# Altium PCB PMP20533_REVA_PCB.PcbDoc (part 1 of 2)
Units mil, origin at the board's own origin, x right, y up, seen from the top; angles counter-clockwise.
Board outline 2795.47 x 1881.89 mil, 4 copper layers (Top Layer, Signal Layer 1, Signal Layer 2, Bottom Layer), stack 40.634 mil thick; 90 components, 59 nets, 312 pads, 73 vias.
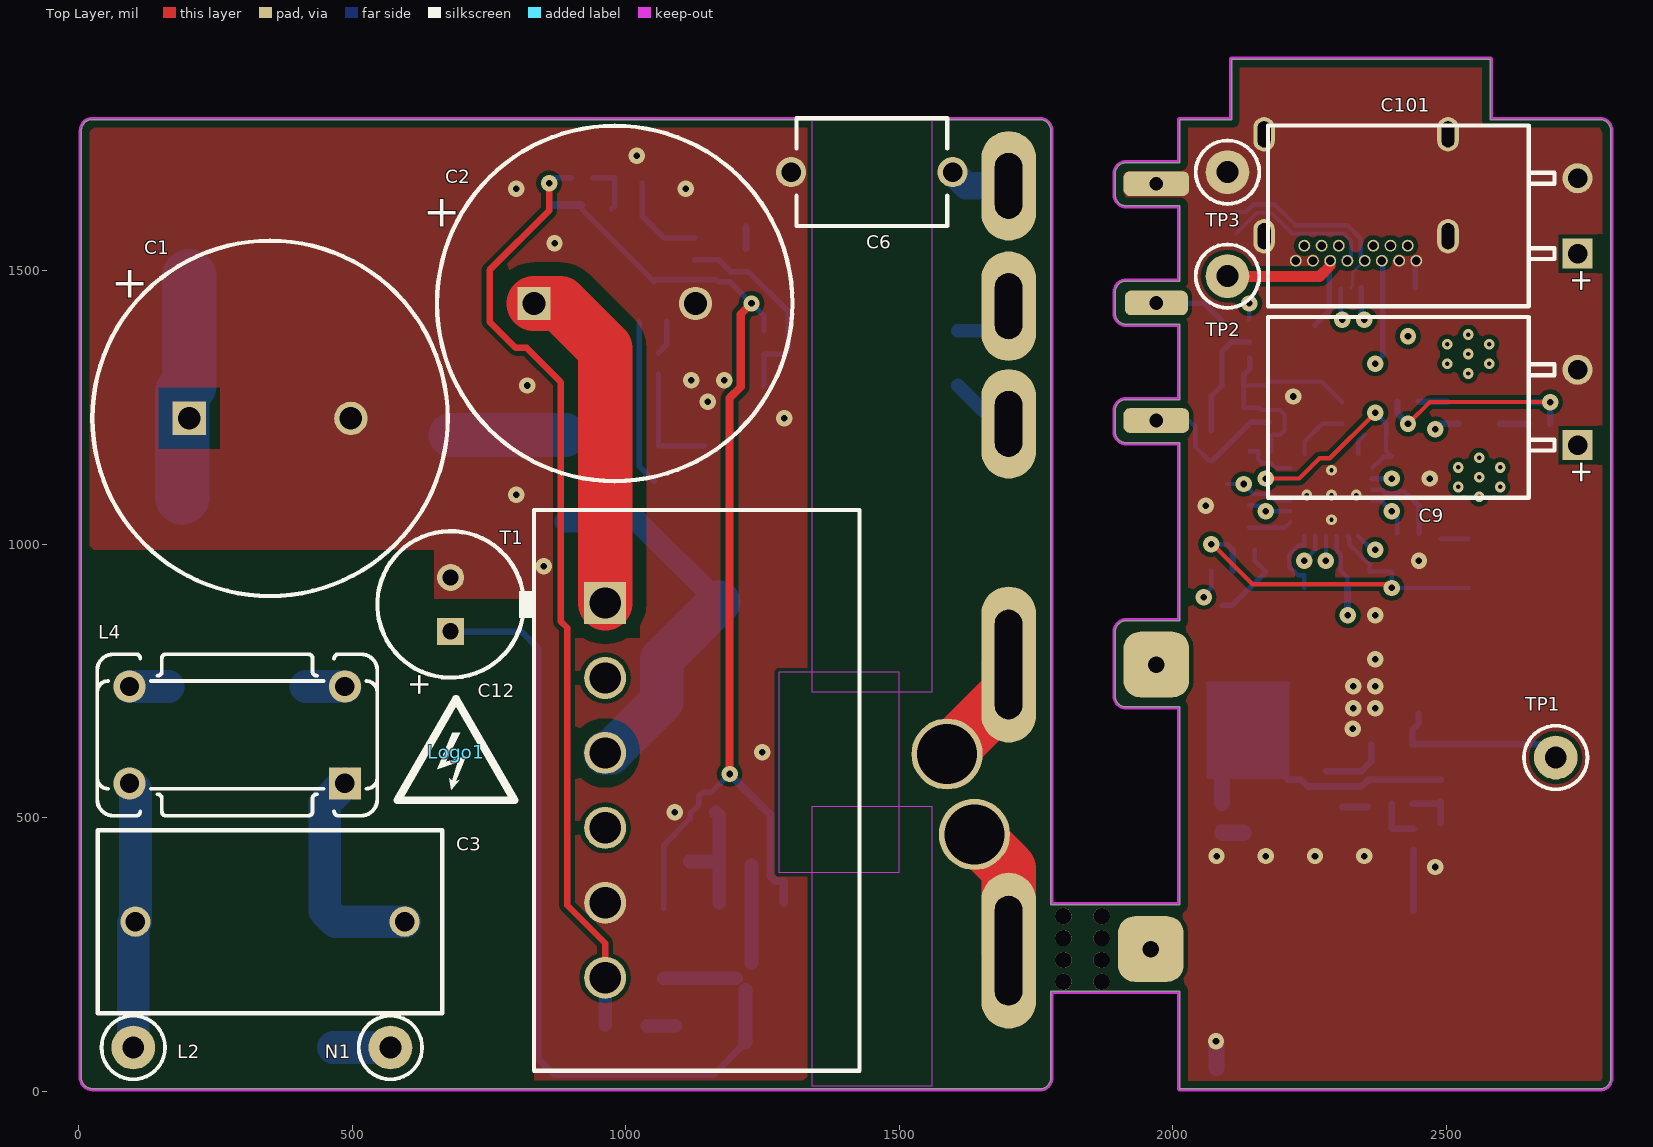
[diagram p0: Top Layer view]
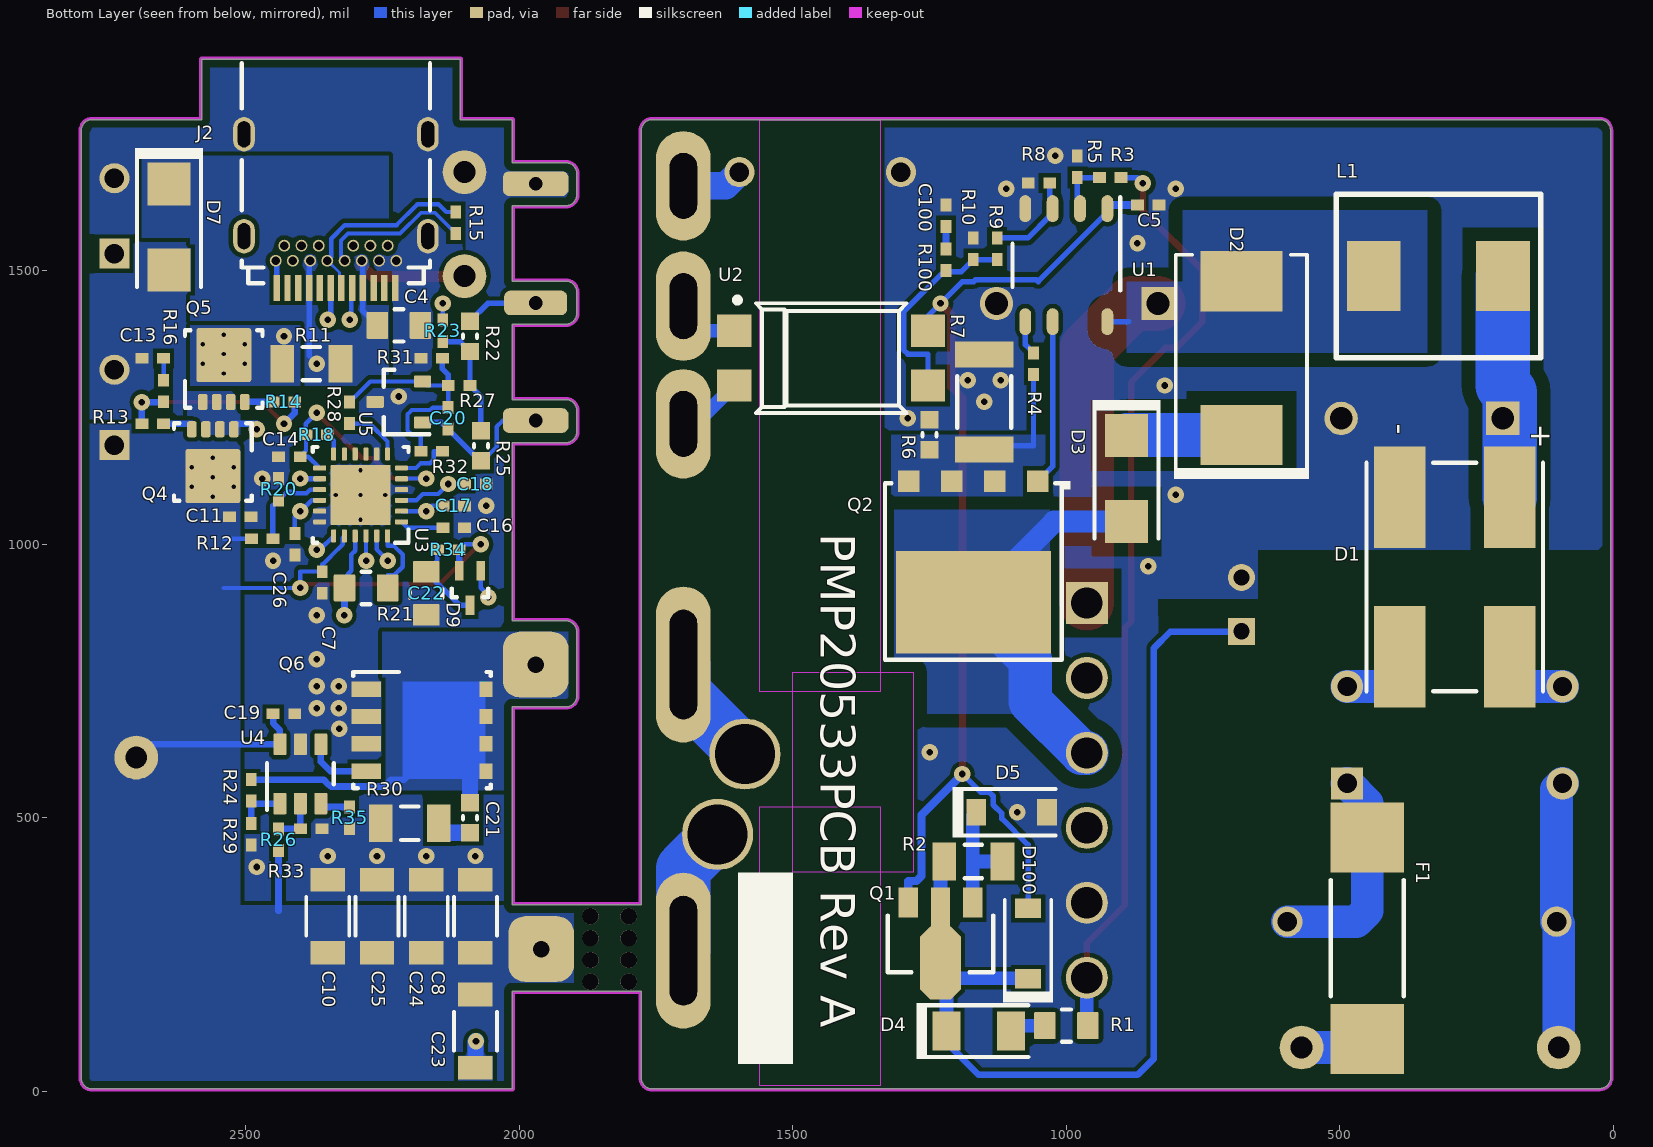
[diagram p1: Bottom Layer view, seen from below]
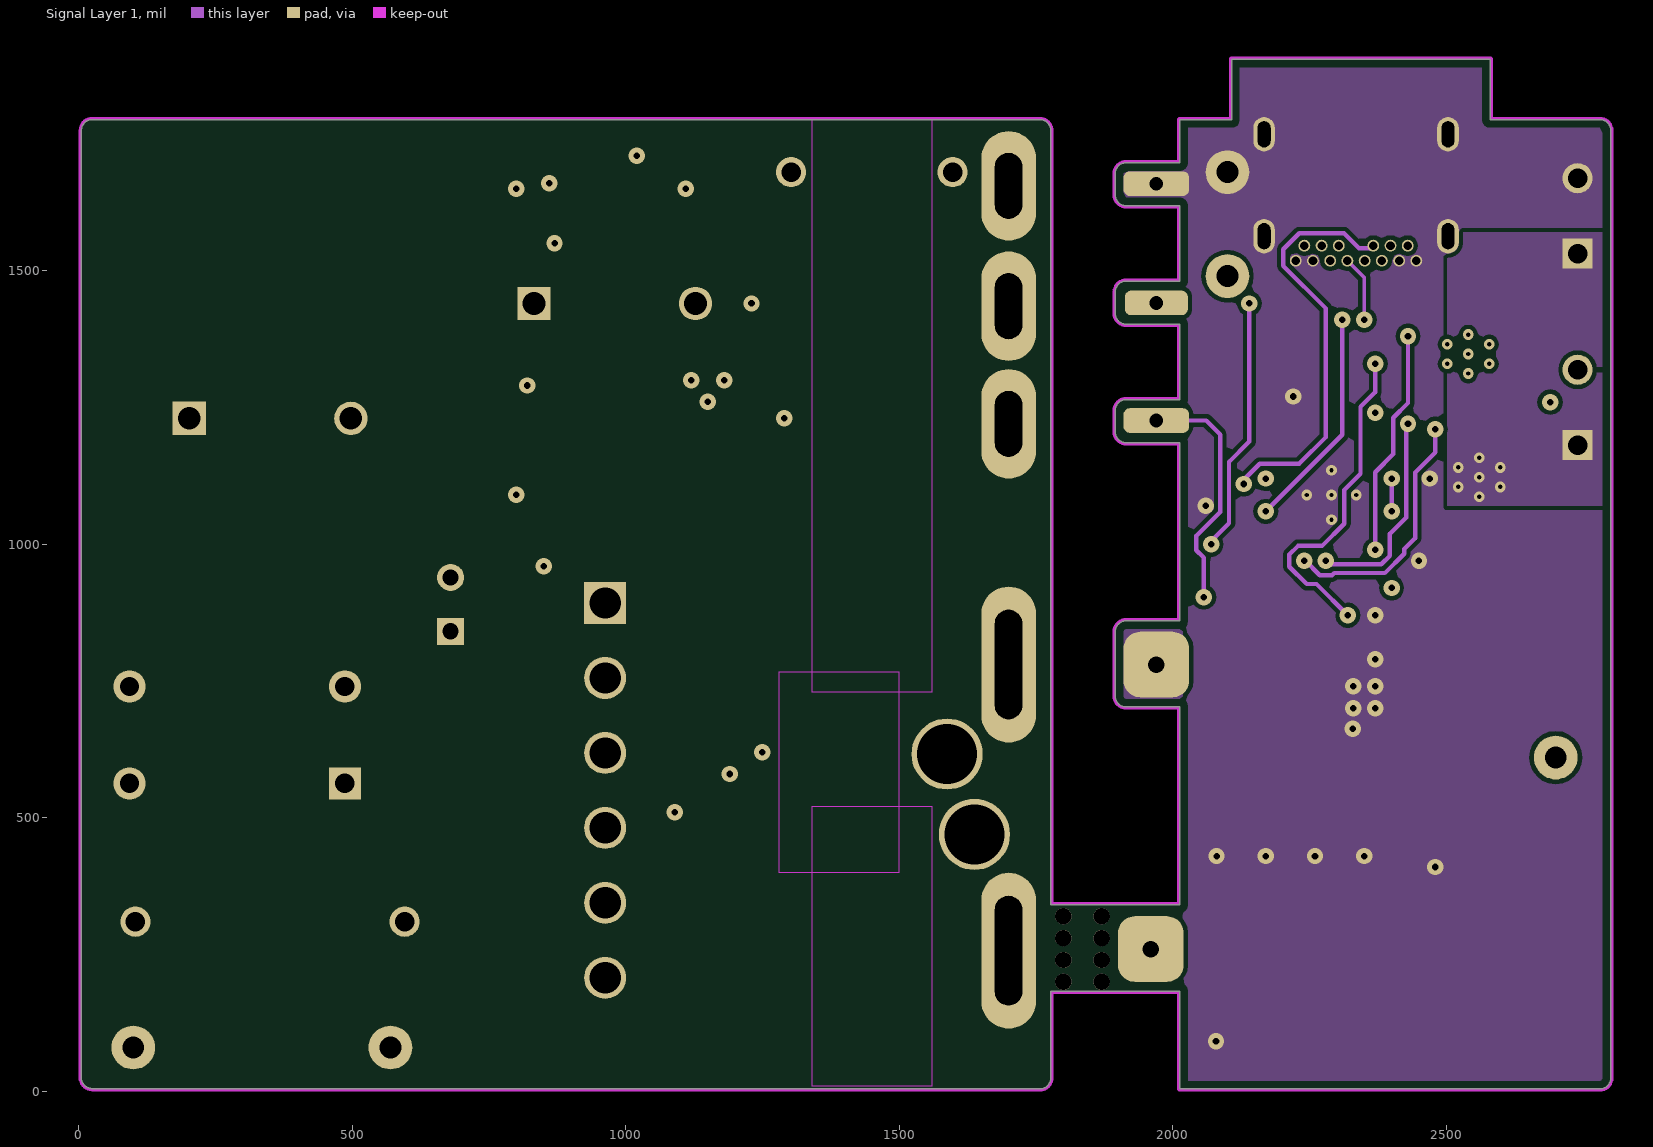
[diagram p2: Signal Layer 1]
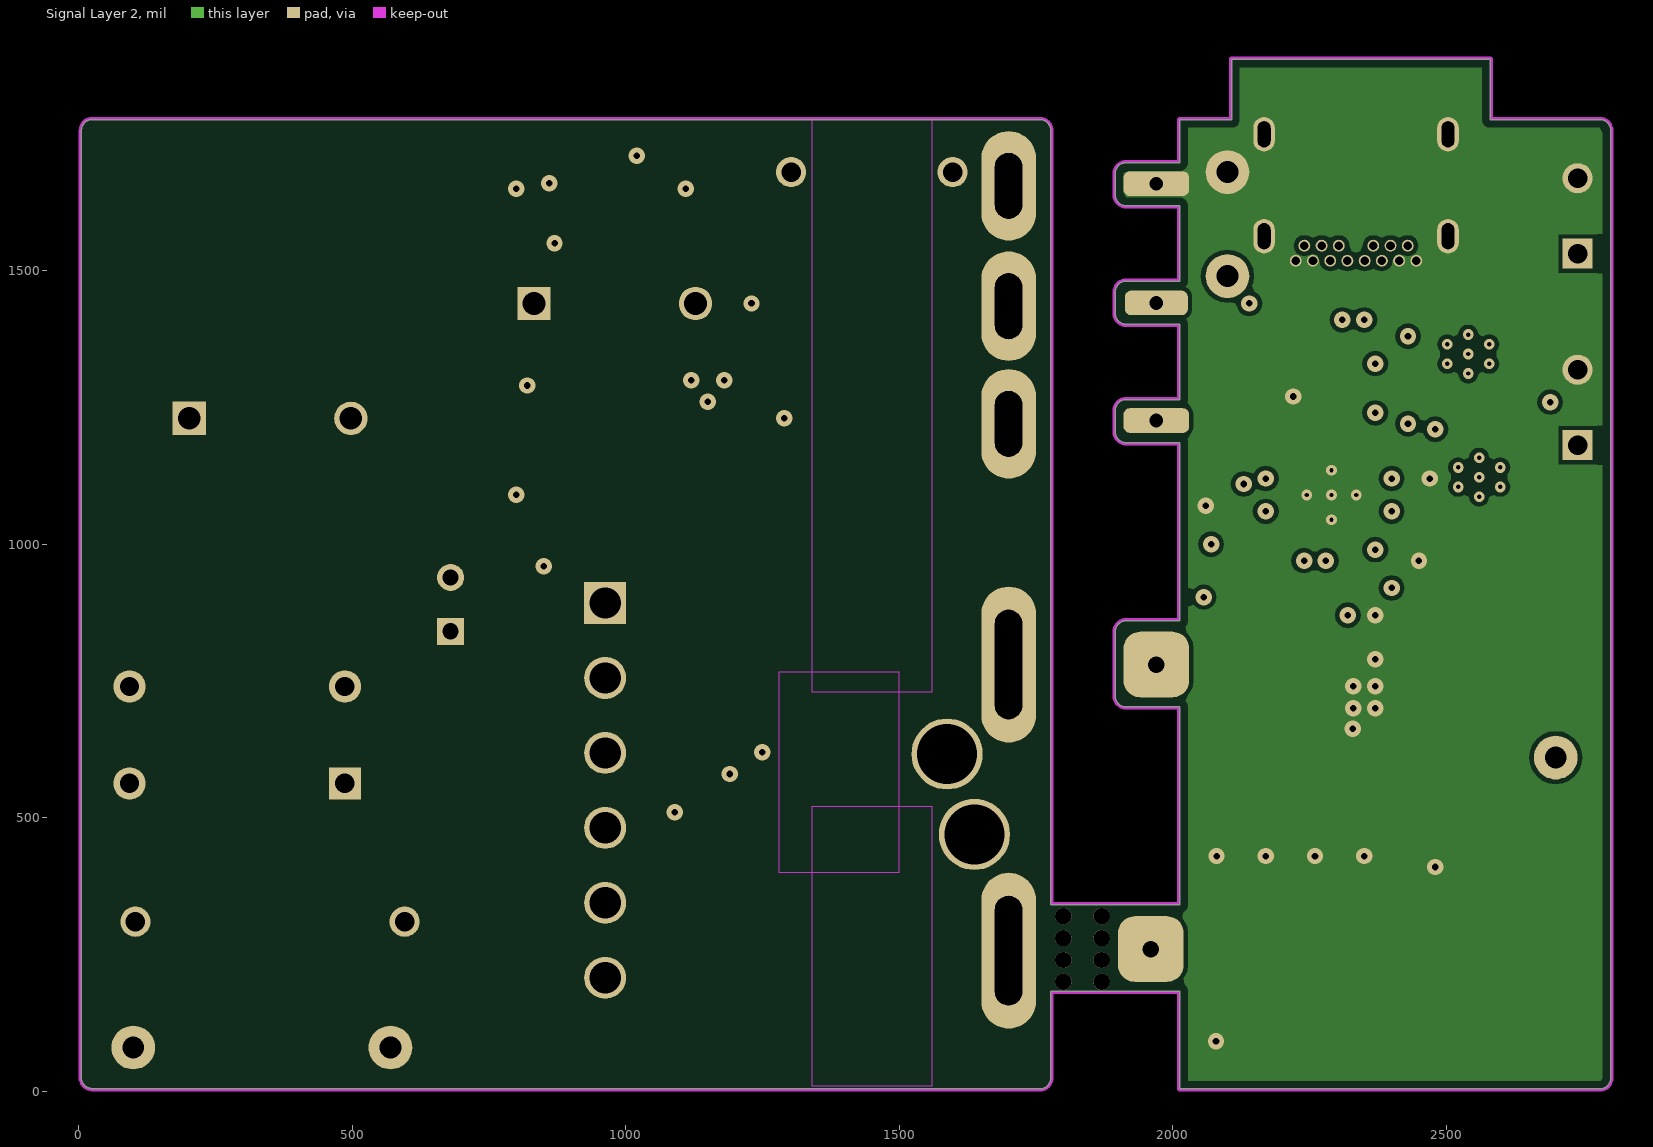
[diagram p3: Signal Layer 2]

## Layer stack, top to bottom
Top Solder: solder mask 0.4, Solder Resist, Dk 3.5
Top Layer: signal copper 1.4
Dielectric1: core 15, FR-4, Dk 4.8
Signal Layer 1: signal copper 1.417
Dielectric 3: prepreg 5, Dk 4.2
Signal Layer 2: signal copper 1.417
Dielectric 2: core 15, Dk 4.2
Bottom Layer: signal copper 1.4
Bottom Solder: solder mask 0.4, Solder Resist, Dk 3.5

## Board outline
25,5 1757.17,4.41 ccw(c1757.17,24.09) 1776.85,24.09 1776.85,183.15 2013.07,183.15 2013.07,4.41 2780.79,4.41 ccw(c2780.79,24.09) 2800.47,24.09 2800.47,1756.38 ccw(c2780.79,1756.38) 2780.79,1776.06 2580,1776.06 2580,1886.3 2107.56,1886.3 2107.56,1776.06 2013.07,1776.06 2013.07,1697.32 1914.65,1697.32 ccw(c1914.65,1677.64) 1894.96,1677.64 1894.96,1638.27 ccw(c1914.65,1638.27) 1914.65,1618.58 2013.07,1618.58 2013.07,1480.79 1914.65,1480.79 ccw(c1914.65,1461.1) 1894.96,1461.1 1894.96,1421.73 ccw(c1914.65,1421.73) 1914.65,1402.05 2013.07,1402.05 2013.07,1264.25 1914.65,1264.25 ccw(c1914.65,1244.57) 1894.96,1244.57 1894.96,1205.2 ccw(c1914.65,1205.2) 1914.65,1185.51 2013.07,1185.51 2013.07,859.92 1914.65,859.92 ccw(c1914.65,840.24) 1894.96,840.24 1894.96,722.13 ccw(c1914.65,722.13) 1914.65,702.44 2013.07,702.44 2013.07,340.63 1776.85,340.63 1776.85,1756.38 ccw(c1757.17,1756.38) 1757.17,1776.06 24.88,1776.06 ccw(c24.88,1756.38) 5.2,1756.38 5,25 ccw(c25,25)

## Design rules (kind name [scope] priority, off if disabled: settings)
AcuteAngle [All] p1: minimum=0.00000000000000E+0000 checktracksonly=FALSE
AssemblyTestPointUsage [All] p1: valid=2
BoardOutlineClearance BoardOutlineClearance_MountingHoles [OnCopper and InComponentClass('Mounting Holes')] p1: gap=15
BoardOutlineClearance BoardOutlineClearance_Poly [OnCopper and InPoly] p2: gap=15
BoardOutlineClearance [OnCopper and Not InComponentClass('Logo') and not InComponentClass('FiducialMark') and not InRegion(1000,500,4000,800)] p3: gap=15
Clearance "Schematic Clearance Constraint_3" [InNet('VDC')] p1: gap=25
Clearance "Schematic Clearance Constraint_2" [InNet('NetC1_1')] p2: gap=25
Clearance "Schematic Clearance Constraint_1" [InNet('NetD2_1')] p3: gap=25
Clearance "Schematic Clearance Constraint" [InNet('NetD3_2')] p4: gap=25
Clearance Clearance_Keepouts [((IsTrack Or IsArc) And Not InPoly) And IsFree and IsKeepOut vs ((IsTrack Or IsArc) And Not InPoly) And IsFree and IsKeepOut] p5: gap=0
Clearance Clearance_Poly [InPolygon] p6: gap=8
Clearance [All] p7: gap=7.87
ComponentClearance ComponentClearance_MountingHoles_FiducialMarks [InComponentClass('Mounting Holes') vs InComponentClass('FiducialMark')] p1: gap=50 collisioncheckmode=3 verticalgap=10 showdistances=FALSE
ComponentClearance ComponentClearance_Shunt [InComponentClass('Header') vs InComponentClass('Shunt')] p2: gap=0 collisioncheckmode=3 verticalgap=0 showdistances=FALSE
ComponentClearance ComponentClearance_Logo [InComponentClass('Logo')] p3: gap=50 collisioncheckmode=3 verticalgap=10 showdistances=FALSE
ComponentClearance ComponentClearance_ScrewToNut [(HasFootprint('NY PMS 440 0025 PH')) vs (HasFootprint('Keystone_1902C'))] p4: gap=5 collisioncheckmode=3 verticalgap=10 showdistances=FALSE
ComponentClearance ComponentClearance_MountingHoles [InComponentClass('Mounting Holes')] p5: gap=250 collisioncheckmode=3 verticalgap=100000 showdistances=FALSE
ComponentClearance ComponentClearance_SmallPassives [HasFootprint('0201*') or HasFootprint('0402*') or HasFootprint('0508') or HasFootprint('0603*') or HasFootprint('0612') or HasFootprint('0805*') or HasFootprint('0815*') or HasFootprint('0830*') or HasFootprint('1206*') or HasFootprint('1210*') or HasFootprint('1808*') or HasFootprint('1812*') or HasFootprint('1825*') or HasFootprint('2010*') or HasFootprint('2220*') or HasFootprint('2225*') or HasFootprint('2512*') or HasFootprint('2728*') or HasFootprint('3518*') vs HasFootprint('0201*') or HasFootprint('0402*') or HasFootprint('0508') or HasFootprint('0603*') or HasFootprint('0612') or HasFootprint('0805*') or HasFootprint('0815*') or HasFootprint('0830*') or HasFootprint('1206*') or HasFootprint('1210*') or HasFootprint('1808*') or HasFootprint('1812*') or HasFootprint('1825*') or HasFootprint('2010*') or HasFootprint('2220*') or HasFootprint('2225*') or HasFootprint('2512*') or HasFootprint('2728*') or HasFootprint('3518*')] p6: gap=14.96 collisioncheckmode=3 verticalgap=10 showdistances=FALSE
ComponentClearance ComponentClearance_THtoSMT [IsThruComponent vs IsSMTComponent] p7: gap=15 collisioncheckmode=3 verticalgap=30 showdistances=FALSE
ComponentClearance ComponentClearance_THtoTH [IsThruComponent vs IsThruComponent] p8: gap=10 collisioncheckmode=3 verticalgap=30 showdistances=FALSE
ComponentClearance [All] p9: gap=15 collisioncheckmode=3 verticalgap=10 showdistances=FALSE
DiffPairsRouting [All] p1: maxlimit=100 minlimit=10 mostfreqgap=10 toplayer_minwidth=15 toplayer_maxwidth=15 toplayer_prefwidth=15 midlayer1_minwidth=15 midlayer1_maxwidth=15 midlayer1_prefwidth=15 midlayer2_minwidth=15 midlayer2_maxwidth=15 midlayer2_prefwidth=15 bottomlayer_minwidth=15 bottomlayer_maxwidth=15 bottomlayer_prefwidth=15 maxuncoupledlength=1000
FabricationTestPointUsage TestPointUsage [All] p1: valid=2 allowmultiple=FALSE
FabricationTestpoint Testpoint [All] p1: side=3 testpointundercomponent=TRUE minsize=40 maxsize=100 preferedsize=60 minholesize=0 maxholesize=40 preferedholesize=32 testpointgrid=1 allowsidetop=TRUE allowsidebottom=TRUE usegrid=TRUE gridtolerance=0.01
FanoutControl Fanout_LCC [IsLCC] p1: bgadir=Out bgaviamode=Centered fanoutstyle=Auto fanoutdirection=Alternating viagrid=1 // Fanout_LCC (Default Rule)
FanoutControl Fanout_BGA [IsBGA] p2: bgadir=Out bgaviamode=Centered fanoutstyle=Auto fanoutdirection=Alternating viagrid=1 // Fanout_BGA (Default Rule)
FanoutControl Fanout_Default [All] p4: bgadir=Out bgaviamode=Centered fanoutstyle=Auto fanoutdirection=Alternating viagrid=1 // Fanout_Default (Default Rule)
FanoutControl Fanout_Small [(CompPinCount < 5)] p5: bgadir=Out bgaviamode=Centered fanoutstyle=Auto fanoutdirection=OutThenIn viagrid=1 // Fanout_Small (Default Rule)
HoleSize [All] p1: absolutevalues=TRUE maxlimit=251 minlimit=7.87 maxpercent=80.000 minpercent=20.000
MinimumAnnularRing MinimumAnnularRing_ThermalPadVias [IsVia and InAnyComponent] p1: minimumring=5.91
MinimumAnnularRing [All] p2: minimumring=5.5
MinimumSolderMaskSliver MinimumSolderMaskSliver_Logo [InComponentClass('Logo') vs InComponentClass('Logo')] p1: minsoldermaskwidth=0.7
MinimumSolderMaskSliver [All] p2: minsoldermaskwidth=1
PlaneConnect [All] p1: planeconnectstyle=Direct reliefexpansion=10 reliefentries=4 reliefconductorwidth=10 reliefairgap=10
PolygonConnect [All] p1: connectstyle=Direct reliefconductorwidth=10 reliefentries=4 polygonreliefangle="90 Angle" airgapwidth=10
RoutingVias ThermalPadVias [IsVia and InAnyComponent] p1: holewidth=7.87 width=19.68 viastyle="Through Hole" minholewidth=7.87 minwidth=19.68 maxholewidth=12.99 maxwidth=23.62
RoutingVias [All] p2: holewidth=16 width=34 viastyle="Through Hole" minholewidth=7.87 minwidth=26 maxholewidth=40 maxwidth=65
SilkToBoardRegionClearance [Not ((IsComment or IsDesignator) And (Hide <> 'False')) and not InRegion(1000,500,4000,800)] p1:
SilkToSilkClearance SilkToSilkClearance_Pb-FreeLogo [(HasFootprint('Pb-Free_Overlay_Medium') OR HasFootprint('Pb-Free_Overlay_Small')) vs (HasFootprint('Pb-Free_Overlay_Medium') OR HasFootprint('Pb-Free_Overlay_Small'))] p1: silktosilkclearance=0
SilkToSilkClearance [All] p2: silktosilkclearance=0.1
SilkToSolderMaskClearance SilkToComponentPadClearance [IsPad and InAnycomponent] p1: minsilkscreentomaskgap=0 clearancetoexposedcopper=TRUE
SilkToSolderMaskClearance "Silk to Solder Mask Opening" [All] p2: minsilkscreentomaskgap=0 clearancetoexposedcopper=FALSE
SolderMaskExpansion [All] p1: expansion=1.97
Width [All] p1: maxlimit=100 minlimit=5 preferedwidth=10 checkconnectedcopper=TRUE
15 further rules are at their usual default settings.

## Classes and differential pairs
component class PMP20533_REVA_pg2: C4 C7 C8 C9 C10 C11 C13 C14 C16 C17 C18 C19 C20 C21 C22 C23 C24 C25 C26 C101 D7 D9 J2 Q4 Q5 Q6 R11 R12 R13 R14 R15 R16 R18 R20 R21 R22 R23 R24 R25 R26 R27 R28 R29 R30 R31 R32 R33 R34 R35 TP1 TP2 TP3 U3 U4 U5

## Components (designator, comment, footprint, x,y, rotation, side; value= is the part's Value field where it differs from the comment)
C1 "EKXG401EC3330ML20S" KXG_1600x2000 350,1230 r0 top
C2 "EKXG401EC3330ML20S" KXG_1600x2000 980,1440 r0 top
C3 "ECQ-U3A104MG" ECQUG_1500x800x1500 350,310 r0 top
C4 "GRM21BR6YA106KE43L" 0805_HV1 2220,1400 r180 bottom
C5 "GRM155R61E105KA12D" 0402L 850,1620 r180 bottom
C6 "DE2E3KY152MN3AM02" KY_700x500x1000 1450,1680 r180 top
C7 "GRM155R71C104KA88D" 0402L 2360,930 r270 bottom
C8 "GRT31CR61E226KE01L" 1206_180 2080,320 r90 bottom
C9 "20SEPF390M" SEPF_E12_HorizontalUP 2740,1250 r90 top
C10 "GRT31CR61E226KE01L" 1206_180 2350,320 r90 bottom
C11 "GRM155R61E105KA12D" 0402L 2510,1050 r180 bottom
C12 "UHE2A150MED" HE_630x1100 680,890 r90 top
C13 "GRM155R71H103KA88D" 0402L 2670,1340 r0 bottom
C14 "GRM155R60J274KE01D" 0402L 2420,1160 r0 bottom
C16 "GRM155R71C104KA88D" 0402L 2120,1030 r180 bottom
C17 "GRM155R71H471KA01D" 0402L 2120,1070 r180 bottom
C18 "GRM155R71H471KA01D" 0402L 2080,1110 r180 bottom
C19 "GRM155R61E105KA12D" 0402L 2430,690 r180 bottom
C20 "GRM155R71E473KA88D" 0402L 2130,1230 r90 bottom
C21 "GRM188R72E471KW07D" 0603L 2090,500 r90 bottom
C22 "GRM21BR6YA106KE43L" 0805_HV1 2170,910 r270 bottom
C23 "GRT31CR61E226KE01L" 1206_180 2080,110 r270 bottom
C24 "GRT31CR61E226KE01L" 1206_180 2170,320 r90 bottom
C25 "GRT31CR61E226KE01L" 1206_180 2260,320 r90 bottom
C26 "GRM155R71C104KA88D" 0402L 2410,1000 r270 bottom
C100 "GRM155R71C104KA88D" 0402L 1220,1600 r90 bottom
C101 "20SEPF390M" SEPF_E12_HorizontalUP 2740,1600 r90 top
D1 "Z4DGP406L-HF" Z4-D 290,940 r270 bottom
D2 "SMCJ150A-TP" SMC 680,1340 r90 bottom
D3 "MURA160T3G" SMA 890,1120 r270 bottom
D4 "CSFMT108-HF" SOD-123H 1160,110 r180 bottom
D5 "MMSZ5248B-7-F" SOD-123 1100,510 r180 bottom
D7 "B340A-13-F" SMA 2640,1580 r270 bottom
D9 "BAT54ST-7-F" SOT-523 2090,920 r270 bottom
D100 "MMSD914T1G" SOD-123 1070,270 r90 bottom
F1 "0443003.DR" FUSE_0443 450,280 r90 bottom
J2 "632 723 300 011" Wurth_632_723_300_011 2335,1885 r0 bottom
L1 "DR73-330-R" DR73 320,1490 r0 bottom
L2 "5001" Keystone5001 100,80 r90 top
L4 "744821201" WE-CMB_XS 290,651.34 r180 top
Logo1 "DANGER HIGH VOLTAGE" IEC_HighVoltage_Small 690,620 r0 top
N1 "5002" Keystone5002 570,80 r0 top
Q1 "FCX493TA" SOT-89-3 1230,270 r270 bottom
Q2 "IPL60R299CP" PG-VSON-4 1170,950 r0 bottom
Q4 "CSD17575Q3" DQG0008A 2560,1150 r270 bottom
Q5 "CSD17575Q3" DQG0008A 2540,1320 r90 bottom
Q6 "FDMS86255" TRANS_NexFET_Q5B 2170,660 r180 bottom
R1 "CRCW08054R99FKEA" 0805_HV1 1000,120 r180 bottom
R2 "CRCW120649K9FKEA" 1206L 1170,420 r180 bottom
R3 "CRCW0402249KFKED" 0402L 920,1670 r180 bottom
R4 "CRCW04021K78FKED" 0402L 1060,1330 r270 bottom
R5 "CRCW040225K5FKED" 0402L 980,1690 r270 bottom
R6 "CRCW0603100RFKEA" 0603L 1250,1200 r270 bottom
R7 "CSRN2010FKR250" 2010L 1150,1260 r270 bottom
R8 "CRCW040210K0FKED" 0402L 1050,1660 r180 bottom
R9 "CRCW040230K1FKED" 0402L 1126.41,1540 r90 bottom
R10 "CRCW040210K0FKED" 0402L 1170,1540 r270 bottom
R11 "WSL12065L000FEA" 1206L 2380,1330 r0 bottom
R12 "CRCW0402140KFKED" 0402L 2470,1010 r180 bottom
R13 "CRCW040210R0JNED" 0402L 2670,1220 r0 bottom
R14 "CRCW040210R0JNED" 0402L 2430,1260 r180 bottom
R15 "CRCW0402100RJNED" 0402L 2116.02,1587.45 r90 bottom
R16 "CRCW04021K00FKED" 0402L 2650,1280 r90 bottom
R18 "CRCW0402100KFKED" 0402L 2370,1200 r180 bottom
R20 "CRCW040286K6FKED" 0402L 2440,1100 r270 bottom
R21 "RG2012P-121-B-T5" 0805_HV1 2280,920 r0 bottom
R22 "CRCW06031K00FKEA" 0603L 2090,1380 r270 bottom
R23 "CRCW04020000Z0ED" 0402L 2140,1390 r90 bottom
R24 "CRCW0402499KFKED" 0402L 2490,550 r90 bottom
R25 "CRCW06031K00FKEA" 0603L 2070,1180 r270 bottom
R26 "CRCW0402402KFKED" 0402L 2440,460 r270 bottom
R27 "CRCW040220K0FKED" 0402L 2110,1290 r180 bottom
R28 "CRCW040212K4FKED" 0402L 2310,1240 r90 bottom
R29 "CRCW040210K0FKED" 0402L 2490,470 r90 bottom
R30 "ERJ-8ENF51R1V" 1206L 2200,490 r180 bottom
R31 "CRCW040220K0FKED" 0402L 2160,1340 r180 bottom
R32 "CRCW04028K25FKED" 0402L 2160,1170 r0 bottom
R33 "CRCW040237K4FKED" 0402L 2380,480 r0 bottom
R34 "CRCW0402100KFKED" 0402L 2130,990 r0 bottom
R35 "CRCW04024K99FKED" 0402L 2310,500 r90 bottom
R100 "CRCW04023K01FKED" 0402L 1220,1520 r270 bottom
T1 "RLTI-1178" Renco_RLTI-1178 1130,550 r0 top
TP1 "VBUS" Keystone5000 2700,610 r0 top
TP2 "VBUS" Keystone5000 2100,1490 r0 top
TP3 "5001" Keystone5001 2100,1680 r0 top
U1 "UCC28740DR" D0007A_L 1000,1510 r270 bottom
U2 "LTV-817S" DIP254P762X350-4 1430,1340 r180 bottom
U3 "TPS25740ARGER" RGE0024F 2290,1090 r0 bottom
U4 "UCC24636DBVR" DBV0006A_N 2400,580 r90 bottom
U5 "TL431AIDBZR" DBZ0003A_L 2220,1260 r0 bottom

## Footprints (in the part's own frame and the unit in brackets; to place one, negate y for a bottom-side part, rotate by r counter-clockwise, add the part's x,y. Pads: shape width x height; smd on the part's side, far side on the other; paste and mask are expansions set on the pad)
0402L [mm] "0402 from SM-752 data"
  rect 0.6x0.5 smd: 1(-0.5,0) 2(0.5,0)
  body extent -0.55,-0.3 0.55,0.3, height 0.6
0603L [mm] "0603 from SM-752 data"
  rect 0.8x0.85 smd: 1(-0.7,0) 2(0.7,0)
  silkscreen extent -0.07,-0.33 0.07,0.33, body extent -0.87,-0.47 0.87,0.47, height 1
0805_HV1 [mm] "Custom footprint based on analyzing multiple manufacturer recommendations"
  rrect10% 1x1.25 smd: 1(-1,0) 2(1,0)
  silkscreen extent -0.2,-0.75 0.2,0.75, body extent -1.1,-0.72 1.1,0.73, height 1.45
1206_180 [mm] "1206_180"
  rect 1.1x1.6 smd: 1(-1.7,0) 2(1.7,0)
  silkscreen extent -0.9,-1 0.9,1, body extent -1.75,-0.95 1.75,0.95, height 1.8
1206L [mm] "1206 from SM-752 data"
  rect 1.1x1.75 smd: 1(-1.35,0) 2(1.35,0)
  silkscreen extent -0.4,-0.77 0.4,0.77, body extent -1.7,-0.9 1.7,0.9, height 1.35
2010L [mm]
  rect 1.2x2.7 smd: 1(-2.2,0) 2(2.2,0)
  silkscreen extent -1.2,-1.25 1.2,1.25, body extent -2.73,-1.45 2.73,1.45, height 1.66
D0007A_L [mm] "SOIC, 7-Leads, Body 4.9x3.9mm, Pitch 1.27mm, IPC High Density"
  oval 1.25x0.55 smd: 1(-2.625,1.905) 2(-2.625,0.635) 3(-2.625,-0.635) 4(-2.625,-1.905) 5(2.625,-1.905) 6(2.625,-0.635) 8(2.625,1.905)
  silkscreen extent -3.15,-2.5 1.17,2.5, body extent -3.01,-2.45 3.01,2.45, height 1.75
DBV0006A_N [mm] "SOT23, 6-Leads, Body 2.9x1.6mm, Pitch 0.95mm, Lead Span 2.8mm, IPC Medium Density"
  rrect17% 1x0.6 smd: 1(-1.375,0.95) 2(-1.375,0) 3(-1.375,-0.95) 4(1.375,-0.95) 5(1.375,0) 6(1.375,0.95)
  silkscreen extent -1.68,-1.55 0.5,1.55, body extent -1.42,-1.46 1.42,1.46, height 1.12
DBZ0003A_L [mm] "SOT23, 3-Leads, Body 2.9x1.3mm, Pitch 0.95mm, Lead Span 2.4mm, IPC High Density"
  rrect18% 0.8x0.55 smd: 1(-1.1,0.95) 2(-1.1,-0.95) 3(1.1,0)
  silkscreen extent -1.43,-1.5 0.7,1.5, body extent -1.26,-1.46 1.26,1.46, height 0.98
DIP254P762X350-4 [mm] "LITE-ON"
  rect 1.6x1.5 smd: 1(-4.5,1.27) 2(-4.5,-1.27) 3(4.5,-1.27) 4(4.5,1.27)
  silkscreen extent -4.47,-2.55 3.5,2.82, body extent -5.23,-2.55 5.23,2.55, height 4.62
DQG0008A [mm] "SMD, 8-Leads, Body 3.3x3.3mm, Pitch 0.65mm"
  rrect45% 0.75x0.44 smd paste-0.05 mask-0.05: 1(-1.525,0.975) 2(-1.525,0.325) 3(-1.525,-0.325) 4(-1.525,-0.975) 5(1.525,-0.975) 6(1.525,-0.325) 7(1.525,0.325) 8(1.525,0.975)
  rrect15% 0.676x1.125 on Bottom Paste: 9(-0.212,-0.663) 9(-0.212,0.662) 9(0.664,-0.663) 9(0.664,0.662)
  rrect6% 1.775x2.45 on Bottom Solder: 9(0.327,0)
  rrect8% 2.5x2.55 smd paste-1.5 mask-1.5: 9(0.65,0)
  rrect29% 0.5x0.34 on Bottom Solder: 9(1.175,-0.975) 9(1.175,-0.325) 9(1.175,0.325) 9(1.175,0.975)
  silkscreen extent -1.8,-1.8 1.8,1.8, body extent -1.65,-1.65 1.65,1.65, height 1.1
DR73 [mm]
  rect 2.5x3.25 smd: 1(-3,0) 2(3,0)
  silkscreen extent -4.75,-3.8 4.75,3.8, body extent -3.8,-3.8 3.8,3.8, height 3.55
ECQUG_1500x800x1500 [mm] "TH, 2-Leads, Body 15x8mm, Pin Spacing 12.5mm"
  round 1.4 hole 0.9: 1(-6.25,0) 2(6.25,0)
  silkscreen extent -8,-4.25 8,4.25, body extent -8,-4.25 8,4.25, height 15.5
FUSE_0443 [mm] "LITTELFUSE"
  rect 3.25x3.43 smd: 1(-4.675,0) 2(4.675,0)
  silkscreen extent -2.7,-1.7 2.7,1.7, body extent -5.05,-1.56 5.05,1.56, height 3.12
HE_630x1100 [mm] "TH, 2-Leads, Dia 6.3mm, Pin Spacing 2.5mm"
  rect 1.25x1.25 hole 0.75: 1(-1.25,0)
  round 1.25 hole 0.75: 2(1.25,0)
  silkscreen extent -3.4,-3.4 3.4,3.4, body extent -3.4,-3.4 3.41,3.4, height 12.51
IEC_HighVoltage_Small [mil]
  silkscreen extent -107,-88 107,97
Keystone5000 [mil] "For Keystone 500x miniature loop terminals"
  round 80 hole 40: 1(0,0)
  silkscreen extent -58,-58 58,58, body extent -49,-49 49,49, height 182
Keystone5001 [mil] "For Keystone 500x miniature loop terminals"
  round 80 hole 40: 1(0,0)
  silkscreen extent -58,-58 58,58, body extent -49,-49 49,49, height 182
Keystone5002 [mil] "For Keystone 500x miniature loop terminals"
  round 80 hole 40: 1(0,0)
  silkscreen extent -58,-58 58,58, body extent -49,-49 49,49, height 182
KXG_1600x2000 [mm] "TH, 2-Leads, Dia 16mm, Pin Spacing 7.5mm"
  rect 1.55x1.55 hole 1.05: 1(-3.75,0)
  round 1.55 hole 1.05: 2(3.75,0)
  silkscreen extent -8.25,-8.25 8.25,8.25, body extent -8.25,-8.25 8.26,8.25, height 21.51
KY_700x500x1000 [mm] "TH, 2- Leads, Body 7x5mm, Pin Spacing 7.5mm"
  round 1.4 hole 0.9: 1(-3.75,0) 2(3.75,0)
  silkscreen extent -3.5,-2.5 3.5,2.5, body extent -4.05,-2.5 4.05,2.5, height 9.97
PG-VSON-4 [mm] "INFINEON TECHNOLOGIES"
  rect 1x1 smd: 1(-3,-4.2) 2(-1,-4.2) 3(1,-4.2) 4(3,-4.2)
  rect 7.2x4.75 smd: 5(0,1.43)
  silkscreen extent -4.5,-4.2 4.1,4.1, body extent -4.05,-4.05 4.05,4.05, height 1.1
Renco_RLTI-1178 [mm] "TH, 8-Leads, Body 595x1025mil, Pitch 137mil"
  rect 1.95x1.95 hole 1.45: 1(-4.255,8.7)
  round 1.95 hole 1.45: 2(-4.255,5.22) 3(-4.255,1.74) 4(-4.255,-1.74) 5(-4.255,-5.22) 6(-4.255,-8.7)
  round 3.3 hole 2.8: A(12.89,-2.045) B(11.62,1.689)
  silkscreen extent -8.25,-13.02 7.56,13.02, body extent -7.56,-13.02 13.96,13.02, height 21.49
RGE0024F [mm] "QFN, 24-Leads, Body 4x4mm, Pitch 0.5mm, Thermal Pad 2.8x2.8mm, TI Recommended"
  rrect42% 0.6x0.24 smd: 1(-1.9,1.25) 2(-1.9,0.75) 3(-1.9,0.25) 4(-1.9,-0.25) 5(-1.9,-0.75) 6(-1.9,-1.25) 13(1.9,-1.25) 14(1.9,-0.75) 15(1.9,-0.25) 16(1.9,0.25) 17(1.9,0.75) 18(1.9,1.25)
  rrect42% 0.24x0.6 smd: 7(-1.25,-1.9) 8(-0.75,-1.9) 9(-0.25,-1.9) 10(0.25,-1.9) 11(0.75,-1.9) 12(1.25,-1.9) 19(1.25,1.9) 20(0.75,1.9) 21(0.25,1.9) 22(-0.25,1.9) 23(-0.75,1.9) 24(-1.25,1.9)
  rrect8% 1.23x1.23 on Bottom Paste: 25(-0.715,-0.715) 25(-0.715,0.715) 25(0.715,-0.715) 25(0.715,0.715)
  rrect4% 2.8x2.8 smd paste-1.4: 25(0,0)
  silkscreen extent -2.22,-2.22 2.22,2.22, body extent -2.07,-2.07 2.08,2.08, height 1.01
SEPF_E12_HorizontalUP [mm] "TH, 2-Leads, Dia 8mm, Lead Spacing 3.5mm"
  rect 1.4x1.4 hole 0.9: 1(-1.75,0)
  round 1.4 hole 0.9: 2(1.75,0)
  silkscreen extent -4.2,1.07 4.2,14.37, body extent -4.22,-0.3 4.28,14.35, height 8.5
SMA [mm] "Molded Diode, 2-Leads, Body 4.3x2.6mm, IPC Medium Density, based on OnSemi component dimensions and land pattern"
  rect 2x2 smd: 1(-2,0) 2(2,0)
  silkscreen extent -3.66,-1.57 2.79,1.57, body extent -2.6,-1.3 2.6,1.3, height 2.42
SMC [mil] "Molded Diode, 2-Leads, Body 6.9x5.8mm, IPC Medium Density, based on OnSemi component dimensions and land patterns"
  rect 110x150 smd: 1(-140.49,0) 2(140.49,0)
  silkscreen extent -221,-123 189,124, body extent -156,-116 156,116, height 91
SOD-123 [mm] "On Semi recommended land pattern"
  rect 0.915x1.22 smd: 1(-1.637,0) 2(1.637,0)
  silkscreen extent -2.74,-1.17 2.03,1.17, body extent -1.93,-0.9 1.93,0.9, height 1.35
SOD-123H [mm] "SMT, 2-Leads, Body 3.5x1.6mm"
  rect 1.3x1.8 smd: 1(-1.5,0) 2(1.5,0)
  silkscreen extent -2.9,-1.3 2.3,1.3, body extent -1.9,-0.9 1.9,0.9, height 1
SOT-89-3 [mm] "SOT, 3-Leads, Body 4.6 x 2.6 mm, Pitch 1.5mm"
  rect 1.4x0.9 smd: 1(-1.9,1.5) 3(-1.9,-1.5)
  rect 1.8x0.9 smd: 2(-1.7,0)
  oct 3.4x1.9 smd: 4(0.9,0)
  silkscreen extent -1.3,-2.45 1.33,2.45, body extent -2.42,-2.28 1.83,2.32, height 1.62
SOT-523 [mm] "From Diodes Inc datasheet component parameters"
  rect 0.9x0.4 smd: 1(-0.8,0.5) 2(-0.8,-0.5) 3(0.8,0)
  silkscreen extent 0.02,-0.85 0.42,0.85, body extent -0.8,-0.8 0.8,0.8, height 0.79
TRANS_NexFET_Q5B [mm] "TI recommended land pattern (nominal) November 2012"
  rect 1.372x0.71 smd paste-0.4: 1(-2.776,1.905) 2(-2.776,0.635) 3(-2.776,-0.635) 4(-2.776,-1.905)
  rect 0.59x0.71 smd paste-0.3: 5(2.776,-1.905) 6(2.776,-0.635) 7(2.776,0.635) 8(2.776,1.905)
  Top Layer region: -1.106,2.26 2.744,2.26 2.744,-2.26 -1.106,-2.26
  silkscreen extent -3.38,-2.7 3,2.7, body extent -3.23,-2.55 2.87,2.55, height 1.06
WE-CMB_XS [mm] "WE-CMB Series Size XS"
  rect 1.5x1.5 hole 0.9: 1(-5,2.25)
  round 1.5 hole 0.9: 2(-5,-2.25) 3(5,-2.25) 4(5,2.25)
  silkscreen extent -6.5,-3.75 6.5,3.75, body extent -6.5,-3.75 6.5,3.75, height 16.24
Wurth_632_723_300_011 [mm] "Connector, Receptacle, USB Type C, R/A"
  rect 0.3x1.2 smd: A1(-2.75,10.58) A2(-2.25,10.58) A3(-1.75,10.58) A4(-1.25,10.58) A5(-0.75,10.58) A6(-0.25,10.58) A7(0.25,10.58) A8(0.75,10.58) A9(1.25,10.58) A10(1.75,10.58) A11(2.25,10.58) A12(2.75,10.58)
  round 0.55 hole 0.4: B1(2.8,9.32) B2(2.4,8.62) B3(1.6,8.62) B4(1.2,9.32) B5(0.8,8.62) B6(0.4,9.32) B7(-0.4,9.32) B8(-0.8,8.62) B9(-1.2,9.32) B10(-1.6,8.62) B11(-2.4,8.62) B12(-2.8,9.32) M1(2,9.32) M2(-2,9.32)
  rrect100% 1x1.6 hole 0.6 slot 1.2 at 90 deg: S1(-4.27,8.18) S2(-4.27,3.45) S3(4.27,3.45) S4(4.27,8.18)
  silkscreen extent -4.37,0.15 4.37,10.36, body extent -4.37,-0.96 4.37,10.83, height 3.07
Z4-D [mm] "SMD, 4-Leads, Body 8.1x10.5mm"
  rect 4.7x2.4 smd: 1(-3.7,2.55) 2(3.7,2.55) 3(3.7,-2.55) 4(-3.7,-2.55)
  silkscreen extent -5.3,-4.1 5.3,4.1, body extent -5.3,-4.1 5.3,4.1, height 1.56

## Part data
C1 C2: "CAP, AL, 33 µF, 400 V, +/- 20%, TH"
C3: "CAP, Film, 0.1 µF, 300 V, +/- 20%, TH"
C4 C22: "CAP, CERM, 10 µF, 35 V, +/- 10%, X5R, 0805"
C5 C11 C19: "CAP, CERM, 1 µF, 25 V, +/- 10%, X5R, 0402"
C6: "CAP, CERM, 1500 pF, 250 V, +/- 20%, E, TH, 2- Leads, Body 7x5mm, Pin Spacing 7.5mm"
C7 C16 C26 C100: "CAP, CERM, 0.1 µF, 16 V, +/- 10%, X7R, 0402"
C8 C10 C23 C24 C25: "CAP, CERM, 22 µF, 25 V, +/- 10%, X5R, AEC-Q200 Grade 3, 1206"
C9 C101: "CAP, Aluminum Polymer, 390 µF, 20 V, +20/-0%, 0.014 ohm, TH"
C12: "CAP, AL, 15 µF, 100 V, +/- 20%, 1.2 ohm, TH"
C13: "CAP, CERM, 0.01 µF, 50 V, +/- 10%, X7R, 0402"
C14: "CAP, CERM, 0.27 µF, 6.3 V, +/- 10%, X5R, 0402"
C17 C18: "CAP, CERM, 470 pF, 50 V, +/- 10%, X7R, 0402"
C20: "CAP, CERM, 0.047 µF, 25 V, +/- 10%, X7R, 0402"
C21: "CAP, CERM, 470 pF, 250 V, +/- 10%, X7R, 0603"
D1: "Diode, P-N-Bridge, 600 V, 4 A, Z4-D"
D2: "Diode, TVS, Uni, 150 V, 1500 W, SMC"
D3: "Diode, Ultrafast, 600 V, 1 A, SMA"
D4: "Diode, Superfast Rectifier, 600 V, 1 A, 3.5x1.6mm"
D5: "Diode, Zener, 18 V, 500 mW, SOD-123"
D7: "Diode, Schottky, 40 V, 3 A, SMA"
D9: "Diode, Schottky, 30 V, 0.2 A, SOT-523"
D100: "Diode, Switching, 100 V, 0.2 A, SOD-123"
F1: "Fuse, 3 A, 250 V, SMD"
J2: "Connector, Receptacle, USB Type C, R/A"
L1: "Inductor, Shielded Drum Core, Ferrite, 33 µH, 1.31 A, 0.166 ohm, SMD"
L2 TP3: "Test Point, Miniature, Black, TH"
L4: "Coupled inductor, 1 mH, 2 A, 0.045 ohm, TH"
Logo1: library part IEC_HighVoltage, "IEC 61010-1 High Voltage Warning"
N1: "Test Point, Miniature, White, TH"
Q1: library part "FCX493TA, Diodes Inc.", "Transistor, NPN, 100 V, 1 A, SOT-89"
Q2: "MOSFET, N-CH, 650 V, 11.1 A, PG-VSON-4"
Q4 Q5: "MOSFET, N-CH, 30 V, 60 A, DQG0008A"
Q6: "MOSFET, N-CH, 150 V, 10 A, SON 5x6mm"
R1: "RES, 4.99, 1%, 0.125 W, 0805"
R2: "RES, 49.9 k, 1%, 0.25 W, 1206"
R3: "RES, 249 k, 1%, 0.063 W, 0402"
R4: "RES, 1.78 k, 1%, 0.063 W, 0402"
R5: "RES, 25.5 k, 1%, 0.063 W, 0402"
R6: "RES, 100, 1%, 0.1 W, 0603"
R7: "RES, 0.25, 1%, 1 W, 2010"
R8 R10 R29: "RES, 10.0 k, 1%, 0.063 W, 0402"
R9: "RES, 30.1 k, 1%, 0.063 W, 0402"
R11: "RES, 0.005, 1%, 0.25 W, 1206"
R12: "RES, 140 k, 1%, 0.063 W, 0402"
R13 R14: "RES, 10, 5%, 0.063 W, 0402"
R15: "RES, 100, 5%, 0.063 W, 0402"
R16: "RES, 1.00 k, 1%, 0.063 W, 0402"
R18 R34: "RES, 100 k, 1%, 0.063 W, 0402"
R20: "RES, 86.6 k, 1%, 0.063 W, 0402"
R21: "RES, 120, 0.1%, 0.125 W, 0805"
R22 R25: "RES, 1.00 k, 1%, 0.1 W, 0603"
R23: "RES, 0, 5%, 0.063 W, 0402"
R24: "RES, 499 k, 1%, 0.063 W, 0402"
R26: "RES, 402 k, 1%, 0.063 W, 0402"
R27 R31: "RES, 20.0 k, 1%, 0.063 W, 0402"
R28: "RES, 12.4 k, 1%, 0.063 W, 0402"
R30: "RES, 51.1, 1%, 0.25 W, 1206"
R32: "RES, 8.25 k, 1%, 0.063 W, 0402"
R33: "RES, 37.4 k, 1%, 0.063 W, 0402"
R35: "RES, 4.99 k, 1%, 0.063 W, 0402"
R100: "RES, 3.01 k, 1%, 0.063 W, 0402"
T1: "Transformer, 110 uH, TH"
TP1 TP2: library part 5000, "Test Point, TH, Miniature, Red"
U1: "Constant-Voltage, Constant-Current Flyback Controller Using Opto-Coupler Feedback, D0007A"
U2: "Optocoupler, 5 kV, 50-600% CTR, SMT"
U3: "USB Power Delivery (PD) Provider-Only and Type-C Downward Facing Port (DFP) Port Controller, RGE0024F"
U4: "SYNCRONOUS RECTIFIER CONTROLLER WITH LOW POWER STANDBY, DBV0006A"
U5: "Adjustable Precision Shunt Regulator, 34 ppm / degC, 100 mA, -40 to 85 degC, 3-pin SOT-23 (DBZ), Green (RoHS & no Sb/Br)"

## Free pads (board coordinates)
  oval 100x285 hole 50 slot 200 at 90 deg: 0(1700,257) 0(1700,780)
  oval 100x200 hole 50 slot 120 at 90 deg: 0(1700,1220) 0(1700,1435) 0(1700,1655)
  round 30 hole 30 unplated: 1(1800,200) 1(1800,240) 1(1800,280) 1(1800,320) 1(1870,200) 1(1870,240) 1(1870,280) 1(1870,320)
  rrect50% 120x120 hole 30: 2(1960,260) 2(1970,780)
  rrect50% 120x45 hole 25: 2(1970,1226) 2(1970,1659)
  rrect50% 115x45 hole 25: 2(1970,1441)

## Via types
v1: diameter 30, hole 12, Top Layer to Bottom Layer, 54 vias
v2: diameter 19.68, hole 7.87, Top Layer to Bottom Layer, 17 vias
v3: diameter 19.68, hole 7.87, Top Layer to Bottom Layer, tented both sides, 2 vias

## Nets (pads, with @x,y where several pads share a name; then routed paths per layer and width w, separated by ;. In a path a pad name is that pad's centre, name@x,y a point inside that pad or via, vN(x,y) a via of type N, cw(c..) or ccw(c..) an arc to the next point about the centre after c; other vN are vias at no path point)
CC1: C17.1 J2.A5 U3.2 | length 544.8
  Signal Layer 1 w8: v1(2170,1060) 2310,1200 v1(2310,1410)
  Bottom Layer w8: C17.1@2139.68,1070 2160,1070 v1(2170,1060) ; v1@2170.47,1060.47 U3.2@2215.2,1060.47 ; J2.A5@2307.37,1466.56 2307.37,1412.63 v1(2310,1410)
CC2: C18.1 J2.B5 U3.3 | length 884.3
  Signal Layer 1 w8: v1(2129.68,1110) 2129.68,1117.69 2158.87,1146.87 2230.95,1146.87 2279.88,1195.8 2279.88,1430.85 2202.06,1508.67 2202.06,1539.29 2231.1,1568.33 2312.9,1568.33 2340.46,1540.77 2360.15,1540.77 2360.89,1540.03 J2.B5@2366.49,1545.63
  Bottom Layer w8: C18.1@2099.68,1110 v1(2129.68,1110) 2147.97,1091.72 2176.29,1091.72 2187.85,1080.16 U3.3@2215.2,1080.16
CTL1: R32.1 U3.6 | length 96.3
  Bottom Layer w8: R32.1@2140.32,1170 2156,1170 2156,1155.24 2162.96,1148.28 2179.72,1148.28 2188.79,1139.21 U3.6@2215.2,1139.21
CTL2: R28.1 U3.7 | length 105.7
  Bottom Layer w8: U3.7@2240.79,1164.8 2240.79,1187.8 2273.31,1220.32 R28.1@2310,1220.32
DN: J2.A7 J2.B7 R15.1 | length 472.3
  Signal Layer 1 w7: J2.B7@2319.25,1518.07 2350,1487.32 v1(2350,1410)
  Bottom Layer w7: R15.1@2116.02,1567.76 2154.02,1605.82 2179.75,1605.82 2217.74,1567.83 2312.7,1567.83 2325.7,1554.83 2325.7,1524.03 2313.29,1524.03 J2.B7@2319.25,1518.07
  Bottom Layer w10: v1@2344.84,1415.16 J2.A7@2344.84,1468.47
DP: J2.A6 J2.B6 R15.2 | length 362.9
  Bottom Layer w5: J2.A6@2325.15,1468.47 2328.56,1471.87 2328.56,1496.39 J2.B6@2350.25,1518.07
  Bottom Layer w8: R15.2@2116.02,1607.13 2133.58,1607.13 2147.65,1621.2 2186.12,1621.2 2224.11,1583.21 2319.06,1583.21 2343.79,1558.48 2343.79,1525.03 J2.B6@2350.74,1518.07
GND: C4.2 C7.2 C8.2 C9.2 C10.2 C11.2 C13.2 C14.2 C16.2 C17.2 C18.2 C19.2 C22.2 C23.2 C24.2 C25.2 C26.2 C101.2 D7.2 J2.A1 J2.A12 J2.B1 J2.B12 J2.M1 J2.M2 J2.S1 J2.S2 J2.S3 J2.S4 pad.2@1970,1659 Q6.1 Q6.2 Q6.3 R20.1 R29.1 R30.1 R31.1 R33.1 R35.1 TP3.1 U3.4 U3.8 U3.17 U3.18 U3.25@2290,1090 U4.5 U5.3 | length 96.7
  Bottom Layer w10: J2.A12@2443.26,1468.47 J2.B1@2443.26,1516.1
  Bottom Layer w30: v1(2078.97,91.67) 2080,90.64 C23.2@2080,43.07
  other v1: 2480,410 2080,430 2170,430 2260,430 2350,430 2329.13,662.68 2330,700 2370,700 2330,740 2370,740 2370,790 2370,870 2450,970 2060,1070 2470,1120 2220,1270
  other v2: 2290,1044.72 2244.72,1090 2290,1090 2335.28,1090 2290,1135.28
GNDA: C6.1 pad.0@1700,1655 | length 112.7
  Bottom Layer w50: C6.1@1597.64,1680 1622.64,1655 pad.0@1700,1655
NetC1_1: C1.1 D1.1 L1.1 | length 409.1
  Bottom Layer w100: D1.1@189.61,1085.67 189.61,1277.24 202.36,1290 L1.1@202.36,1489.53
NetC3_1: C3.1 L2.1 L4.4 | length 488.9
  Bottom Layer w60: L4.4@93.15,562.76 103.94,551.97 C3.1@103.94,310 100,306.06 L2.1@100,80
NetC3_2: C3.2 F1.2 L4.1 | length 402.4
  Bottom Layer w60: L4.1@486.85,562.76 450,525.91 F1.2@450,464.06 450,330 470,310 C3.2@596.06,310
NetC12_1: C12.1 D4.1 D100.1 Q1.2 Q1.4 R2.1 | length 1746
  Bottom Layer w12: C12.1@680,840.79 680.79,840 810,840 840,810 840,60 870,30 1160,30 D4.1@1219.06,89.06
  Bottom Layer w25: D100.1@1070,206.85 Q1.4@1202.28,206.85 ; D4.1@1219.06,89.06 D4.1@1219.06,110 Q1.4@1219.06,185.51 ; Q1.4@1230,234.57 Q1.2@1230,336.93 R2.1@1230,413.15
NetC13_1: C13.1 R16.2 | length 40
  Bottom Layer w8: R16.2@2650,1299.69 C13.1@2650,1339.68
NetC14_1: C14.1 R18.1 U3.5 U3.13 | length 430.9
  Top Layer w8: v1(2170,1120) 2231.29,1120 2268.28,1156.99 2286.99,1156.99 v1(2370,1240)
  Bottom Layer w8: v1(2170,1120) U3.5@2214.72,1120 ; U3.13@2364.8,1139.21 2385.59,1160 C14.1@2400.32,1160 2389.68,1170.63 R18.1@2389.68,1200 ; v1(2370,1240) 2390,1220 R18.1@2390,1200.32
NetC16_1: C16.1 U3.1 | length 80
  Bottom Layer w8: C16.1@2139.68,1030 2204.41,1030 U3.1@2215.2,1040.79
NetC20_2: C20.2 R27.1 R28.2 R31.2 R32.2 U5.2 | length 458.9
  Bottom Layer w8: R32.2@2179.69,1170 2179.69,1197.31 2182.27,1199.9 2196.22,1199.9 2204.32,1207.99 2204.32,1237.2 2196.22,1245.3 2162.69,1245.3 2158.31,1249.69 C20.2@2130,1249.69 2130,1289.68 R27.1@2129.68,1290 2169.29,1290 U5.2@2176.69,1297.4 2272.28,1297.4 R28.2@2310,1259.69
  Bottom Layer w10: R27.1@2129.68,1290 2129.68,1309.68 2140.31,1320.31 R31.2@2140.31,1340
NetC21_1: C21.1 R30.2 | length 39.3
  Bottom Layer w30: C21.1@2090,472.44 R30.2@2129.29,472.44
NetC22_1: C22.1 D9.3 R34.2 | length 154.3
  Bottom Layer w8: R34.2@2149.69,990 2149.69,969.68 C22.1@2170,949.37
  Bottom Layer w10: D9.3@2090,888.5 2109.13,888.5 C22.1@2170,949.37
NetC26_1: C26.1 U3.14 U3.16 | length 168.6
  Signal Layer 1 w8: v1(2400,1060) v1(2400,1120)
  Bottom Layer w8: U3.16@2364.8,1080.16 2379.39,1080.16 2399.55,1060 v1(2400,1060) ; C26.1@2410,1019.68 v1@2410,1050
  Bottom Layer w10: U3.14@2364.8,1119.53 v1@2399.53,1119.53
NetC100_1: C100.1 R100.1 | length 40.6
  Bottom Layer w12: R100.1@1220,1539.68 C100.1@1220,1580.32
NetD1_2: D1.2 L4.3 | length 70.9
  Bottom Layer w60: L4.3@93.15,739.92 D1.2@164.02,739.92
NetD1_3: D1.3 L4.2 | length 70.9
  Bottom Layer w60: D1.3@415.98,739.92 L4.2@486.85,739.92
NetD2_1: D2.1 D3.1 | length 209.2
  Bottom Layer w80: D2.1@680,1199.51 D3.1@889.23,1199.51
NetD3_2: D3.2 Q2.5 T1.3 | length 707.7
  Bottom Layer w40: D3.2@890,1041.26 1022.44,1041.26 Q2.5@1170,893.7
  Bottom Layer w80: T1.3@962.5,618.5 971.71,618.5 1065.89,712.68 1065.89,789.59 Q2.5@1170,893.7
NetD4_2: D4.2 R1.1 | length 51.6
  Bottom Layer w25: R1.1@1039.37,120 D4.2@1090.94,120
NetD5_1: D5.1 Q1.1 R2.2 | length 222
  Bottom Layer w25: R2.2@1116.85,420 1170.94,420 ; D5.1@1164.47,510 1170.94,503.52 1170.94,420 ; Q1.1@1170.94,344.8 1170.94,420
NetF1_1: F1.1 N1.1 | length 104.1
  Bottom Layer w60: F1.1@465.94,80 N1.1@570,80
NetQ2_1: Q2.1 U1.6 | length 302.4
  Bottom Layer w10: U1.6@1025,1406.65 1025,1142.24 Q2.1@1051.89,1115.35
NetQ2_2: Q2.2 Q2.3 Q2.4 R4.2 R6.2 R7.2 | length 213.7
  Bottom Layer w10: R4.2@1060,1310.31 1060,1180 R7.2@1143.39,1180
NetQ4_1: Q4.1 Q4.2 Q4.3 Q5.1 Q5.2 Q5.3 U3.23 | length 556.8
  Signal Layer 1 w8: v1(2240,970) 2241.99,970 2268.87,943.13 2291.13,943.13 2295.26,947.25 2387.71,947.25 2423.13,982.67 2423.13,991.13 2443.13,1011.13 2443.13,1131.13 2480,1168.01 v1(2480,1210)
  Bottom Layer w8: v1(2240,970) 2260.47,990.47 U3.23@2260.47,1015.2
  Bottom Layer w12: v1@2480,1220 Q4.1@2521.57,1220
NetQ4_4: Q4.4 R13.1 | length 51.9
  Bottom Layer w12: Q4.4@2598.39,1220.04 R13.1@2650.32,1220
NetQ5_4: Q5.4 R14.1 | length 51.9
  Bottom Layer w12: R14.1@2449.68,1260 Q5.4@2501.61,1259.96
NetQ5_5: Q5.5 Q5.6 Q5.7 Q5.8 Q5.9@2540,1345.59 R11.2 U3.19 | length 456.1
  Signal Layer 1 w8: v1(2370,990) 2370,1131.65 2403.13,1164.78 2403.13,1231.13 2430,1258.01 v1(2430,1380)
  Bottom Layer w8: U3.19@2339.21,1015.2 2364.41,990 v1(2370,990)
  other v2: 2540,1311.83 2501.61,1329.65 2578.39,1329.65 2540,1347.46 2501.61,1365.28 2578.39,1365.28
  other v3: 2540,1383.09
NetQ6_4: Q6.4 U4.4 | length 122.1
  Bottom Layer w12: Q6.4@2279.3,585 2345,585 2362.6,602.6 U4.4@2362.6,634.13
NetR1_2: R1.2 R3.2 T1.6 | length 1726.8
  Top Layer w12: v1(860,1660) 860,1609.64 751.36,1501 751.36,1406.45 798.81,1359 818.81,1359 881.5,1296.31 881.5,858.95 893.11,847.33 893.11,339.98 962.5,270.59 T1.6@962.5,207.5
  Bottom Layer w10: v1(860,1660) 870,1670 R3.2@900.31,1670
  Bottom Layer w25: R1.2@962.5,121.87 T1.6@962.5,207.5
NetR3_1: R3.1 R5.2 U1.2 | length 98.6
  Bottom Layer w10: R3.1@939.68,1670 979.69,1670 979.69,1618.03 U1.2@975,1613.35
NetR4_1: R4.1 U1.5 | length 63.2
  Bottom Layer w10: R4.1@1060,1349.68 1075,1364.68 U1.5@1075,1406.65
NetR8_2: R8.2 R9.2 U1.3 | length 173
  Bottom Layer w10: R8.2@1030.31,1660 1030.31,1599.69 1070.31,1559.69 R9.2@1126.41,1559.69
NetR9_1: R9.1 R10.2 R100.2 U2.3 | length 385.1
  Bottom Layer w10: R9.1@1126.41,1520.32 R10.2@1170,1520.31 1192.44,1497.87 1224.19,1497.87 1297.2,1424.86 1297.2,1355.14 1289.66,1347.6 1252.83,1347.6 U2.3@1252.83,1290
